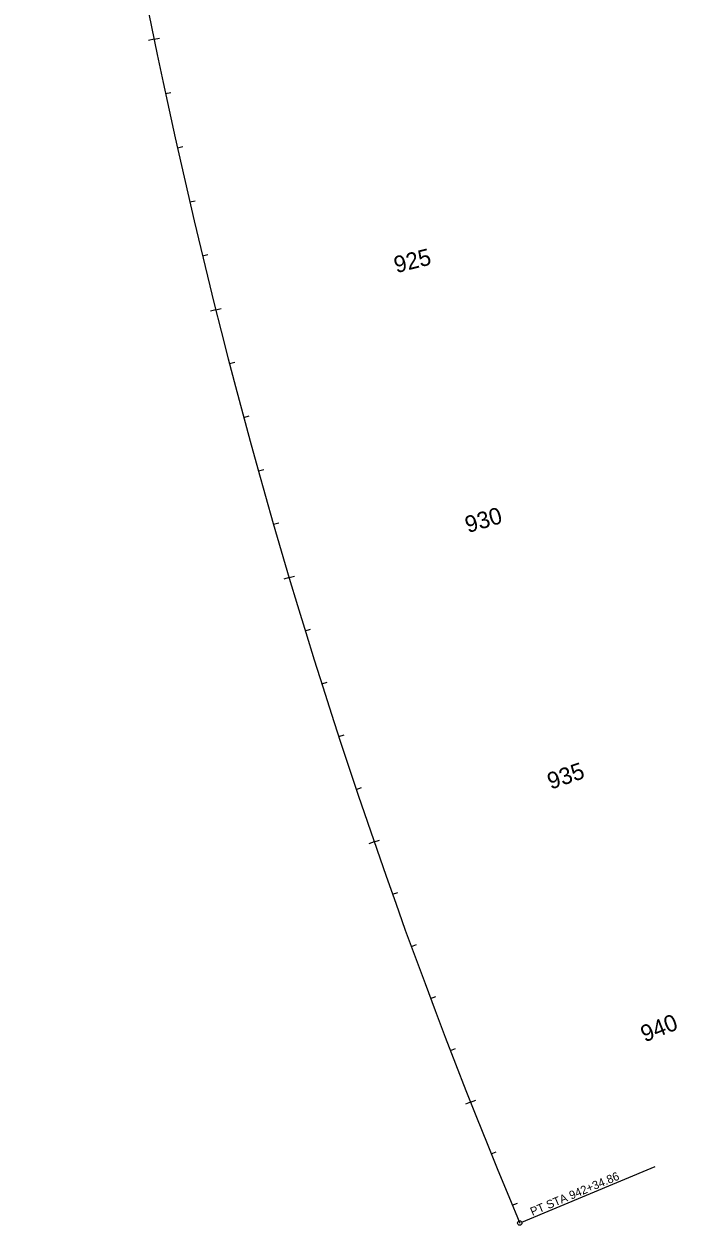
# Model space of a CAD drawing. Extents: x 2820825 to 2825694, y 116785 to 142398.
# Drawn here: x 2820834 to 2822009, y 125379 to 127539 of the extents above; entities that cross this region are included whole.
import ezdxf

# ---------------------------------------------------------------- set-up
doc = ezdxf.new("R2010")
doc.units = 0
for name, color, linetype in [('Default', 7, 'Continuous'), ('Roadway-Centerline main', 7, 'Continuous'), ('Roadway-Curve pc pt', 7, 'Continuous')]:
    doc.layers.add(name, color=color, linetype=linetype)

msp = doc.modelspace()

# ---------------------------------------------------------------- linework, layer by layer
at = {"layer": 'Default'}
msp.add_arc((2832333.7, 129820.2), 11500, 170.03806, 202.7163, dxfattribs=at)
at = {"layer": 'Roadway-Centerline main'}
for p, q in [((2821067.8, 127511.5), (2821058, 127509.4)), ((2821067.8, 127511.5), (2821077.6, 127513.5)), ((2821088.3, 127413.6), (2821098.1, 127415.7)), ((2821109.7, 127315.9), (2821119.5, 127318.1)), ((2821131.9, 127218.4), (2821141.6, 127220.6)), ((2821154.9, 127121.1), (2821164.7, 127123.4)), ((2821178.8, 127024), (2821188.5, 127026.4)), ((2821178.8, 127024), (2821169.1, 127021.5)), ((2821203.6, 126927.1), (2821213.3, 126929.6)), ((2821229.2, 126830.4), (2821238.8, 126833)), ((2821255.6, 126734), (2821265.2, 126736.6)), ((2821282.8, 126637.7), (2821292.4, 126640.5)), ((2821310.9, 126541.8), (2821301.3, 126538.9)), ((2821310.9, 126541.8), (2821320.5, 126544.6)), ((2821339.8, 126446), (2821349.4, 126449)), ((2821369.6, 126350.6), (2821379.1, 126353.6)), ((2821400.2, 126255.4), (2821409.7, 126258.5)), ((2821431.6, 126160.4), (2821441.1, 126163.6)), ((2821463.8, 126065.8), (2821454.4, 126062.5)), ((2821463.8, 126065.8), (2821473.3, 126069)), ((2821496.9, 125971.4), (2821506.3, 125974.7)), ((2821530.8, 125877.3), (2821540.2, 125880.7)), ((2821565.5, 125783.5), (2821574.8, 125787)), ((2821601, 125690), (2821610.3, 125693.6)), ((2821637.3, 125596.9), (2821646.6, 125600.5)), ((2821637.3, 125596.9), (2821628, 125593.2)), ((2821674.4, 125504), (2821683.7, 125507.8)), ((2821712.4, 125411.5), (2821721.6, 125415.3))]:
    msp.add_line(p, q, dxfattribs=at)
msp.add_arc((2832333.7, 129820.2), 11500, 170.03806, 202.7163, dxfattribs=at)
at = {"layer": 'Roadway-Curve pc pt'}
msp.add_line((2821729.5, 125380.9), (2821969.7, 125481.4), dxfattribs=at)
msp.add_circle((2821725.8, 125379.3), 4, dxfattribs=at)

# ---------------------------------------------------------------- texts
at = {"layer": 'Roadway-Centerline main'}
for s, rotation, p in [(' 925', 14.0728, (2821492.9, 127087.2)), (' 930', 16.5639, (2821621.9, 126618.6)), (' 935', 19.055, (2821771.2, 126156.1)), (' 940', 21.5462, (2821940.4, 125700.4))]:
    msp.add_text(s, height=30, rotation=rotation, dxfattribs=at).set_placement(p)
at = {"layer": 'Roadway-Curve pc pt'}
msp.add_text('PT STA 942+34.86', height=15, rotation=22.7163, dxfattribs=at).set_placement((2821748.6, 125392.1))

doc.saveas('drawing.dxf')
